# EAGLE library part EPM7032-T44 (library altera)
EPM7032 MAX 7000 family
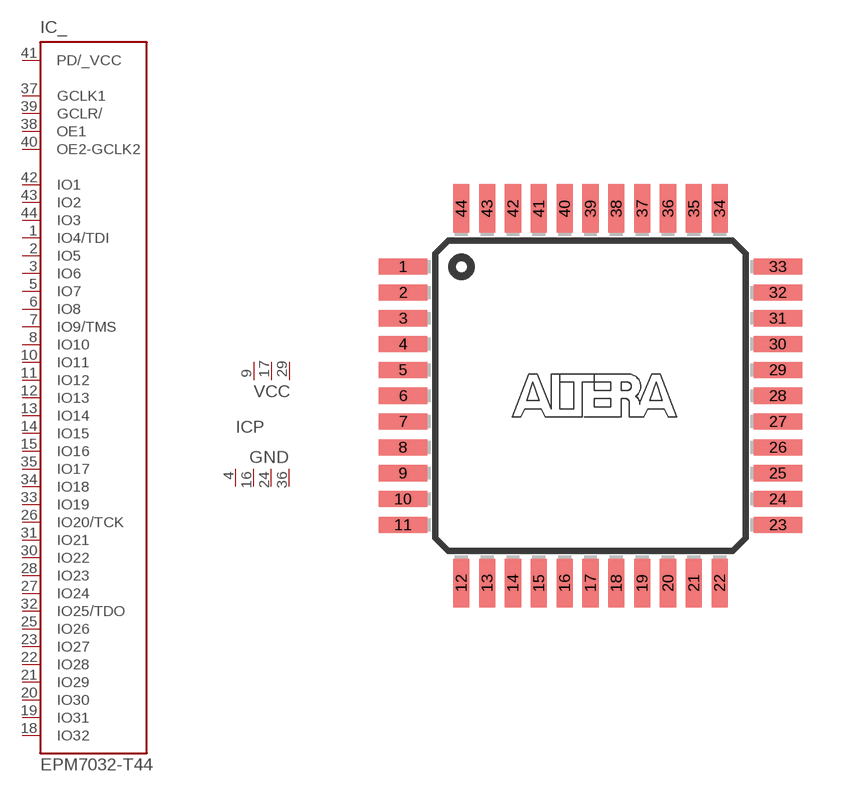
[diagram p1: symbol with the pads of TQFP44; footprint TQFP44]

Designator prefix IC; gates _=EPM7032 P=PWR3-4

## EPM7032-T44  [TQFP44]
1  _:IO4/TDI
2  _:IO5
3  _:IO6
4  P:GND  pwr
5  _:IO7
6  _:IO8
7  _:IO9/TMS
8  _:IO10
9  P:VCC  pwr
10  _:IO11
11  _:IO12
12  _:IO13
13  _:IO14
14  _:IO15
15  _:IO16
16  P:GND  pwr
17  P:VCC  pwr
18  _:IO32
19  _:IO31
20  _:IO30
21  _:IO29
22  _:IO28
23  _:IO27
24  P:GND  pwr
25  _:IO26
26  _:IO20/TCK
27  _:IO24
28  _:IO23
29  P:VCC  pwr
30  _:IO22
31  _:IO21
32  _:IO25/TDO
33  _:IO19
34  _:IO18
35  _:IO17
36  P:GND  pwr
37  _:GCLK1  in
38  _:OE1  in
39  _:GCLR/  in
40  _:OE2-GCLK2  in
41  _:PD/_VCC  pas
42  _:IO1
43  _:IO2
44  _:IO3

## Footprint TQFP44 (pad centres in mm)
Plastic Thin Quad Flat Pack
smd 1.5 x 0.5: 1 -5.8,4; 2 -5.8,3.2; 3 -5.8,2.4; 4 -5.8,1.6; 5 -5.8,0.8; 6 -5.8,0; 7 -5.8,-0.8; 8 -5.8,-1.6; 9 -5.8,-2.4; 10 -5.8,-3.2; 11 -5.8,-4; 23 5.8,-4; 24 5.8,-3.2; 25 5.8,-2.4; 26 5.8,-1.6; 27 5.8,-0.8; 28 5.8,0; 29 5.8,0.8; 30 5.8,1.6; 31 5.8,2.4; 32 5.8,3.2; 33 5.8,4
smd 0.5 x 1.5: 12 -4,-5.8; 13 -3.2,-5.8; 14 -2.4,-5.8; 15 -1.6,-5.8; 16 -0.8,-5.8; 17 0,-5.8; 18 0.8,-5.8; 19 1.6,-5.8; 20 2.4,-5.8; 21 3.2,-5.8; 22 4,-5.8; 34 4,5.8; 35 3.2,5.8; 36 2.4,5.8; 37 1.6,5.8; 38 0.8,5.8; 39 0,5.8; 40 -0.8,5.8; 41 -1.6,5.8; 42 -2.4,5.8; 43 -3.2,5.8; 44 -4,5.8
